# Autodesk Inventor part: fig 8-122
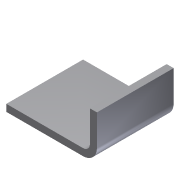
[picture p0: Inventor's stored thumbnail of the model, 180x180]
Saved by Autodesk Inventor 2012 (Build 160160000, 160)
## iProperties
Created: 2009-09
Part Number: fig 8-122
Document SubType Name: Modeling
Designer: Sham
Density: 1 g/cm^3
Material: Default
Author: Sham
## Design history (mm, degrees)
sketch "Sketch1"
  geometry: L1 (-33.976, 22)-(0, 22); L2 (0, 22)-(0, 0); L3 (0, 0)-(-33.976, 0); L4 (-33.976, 0)-(-33.976, 22)
  constraints: 8 end point, 2 parallel, 1 horizontal, 1 perpendicular
extrude "Extrusion1" new body sketch "Sketch1" distance "d0" = 2; taper "d1" = 0 deg
sketch "Sketch2"
  geometry: L1 (-12, 22)-(-12, 0)
  constraints: 2 end point
feature "Bend Part1" sketch "Sketch2" dims "d5" = 90 deg, "d6" = 2
body "Solid1"
